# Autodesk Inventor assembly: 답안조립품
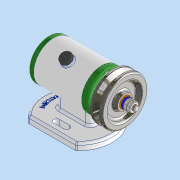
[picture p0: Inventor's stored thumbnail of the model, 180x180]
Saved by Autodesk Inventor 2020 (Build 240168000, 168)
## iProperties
Created: 2022-02
Part Number: 답안조립품
Document SubType Name: Assembly
Designer: 602-04
Author: 602-04
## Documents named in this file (14)
- C:\Users\602-04\Desktop\720206V1026\답안조립품.iam
- C:\Users\602-04\Desktop\720206V1026\본체.ipt
- C:\Users\602-04\Desktop\720206V1026\베어링 6002.ipt
- C:\Users\602-04\Desktop\720206V1026\축.ipt
- C:\Users\602-04\Desktop\720206V1026\앞커버.ipt
- C:\Users\602-04\Desktop\720206V1026\오일 실 15 x 25 x 7.ipt
- C:\Users\602-04\Desktop\720206V1026\볼트 M4 x 10.ipt
- C:\Users\602-04\Desktop\720206V1026\키 3 x 3 x 12.ipt
- C:\Users\602-04\Desktop\720206V1026\V벨트풀리.ipt
- C:\Users\602-04\Desktop\720206V1026\평와셔 8 x 17.ipt
- C:\Users\602-04\Desktop\720206V1026\스프링와셔 8.ipt
- C:\Users\602-04\Desktop\720206V1026\너트 M8.ipt
- C:\Users\602-04\Desktop\720206V1026\뒤커버.ipt
- C:\Users\602-04\Desktop\720206V1026\고무 캡.ipt
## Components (2 placed, 2 different names)
1. V벨트풀리:1
2. 고무 캡:1 — 각도:1
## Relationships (1: Angle 1)
- 각도:1 [Angle]: 고무 캡:1
